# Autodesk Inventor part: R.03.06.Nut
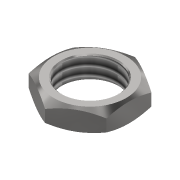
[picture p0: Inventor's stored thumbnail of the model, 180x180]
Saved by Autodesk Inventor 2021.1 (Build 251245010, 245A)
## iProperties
Created: 2021-02
Part Number: R.03.06.Nut
Material: Stainless Steel
Document SubType Name: Modeling
Designer: Михальчик
Density: 8 g/cm^3
Appearance: Semi-Polished
Author: Михальчик
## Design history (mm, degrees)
sketch "Sketch1"
  geometry: L1 (0, 0)-(0, 19.932); L2 (5, 0)-(8.5, 0); L3 (8.5, 0)-(8.5, 4); L4 (8.5, 4)-(5, 4); L5 (5, 4)-(5, 0); L6 (6.5, 4)-(8.5, 2.845); L7 (8.5, 1.155)-(6.5, 0)
  constraints: 14 end point, 5 point on line, 2 parallel, 1 equal length, 1 horizontal, 1 perpendicular, 1 vertical
  dimensions: "d0" = 10 diameter of L5 L1; "d1" = 17 diameter of L3 L1; "d2" = 4 distance of L2.end L3.end; "d3" = 150 deg angle of L4 L6; "d4" = 13 diameter of L6.start L1; "d5" = 30 deg angle of L2 L7
revolve "Revolution1" sketch "Sketch1" stored, may be unused: angle "d6" = 90 deg
thread "Thread1" dims "d7" = 4, "d8" = 0
chamfer "Chamfer1" distance "d9" = 0.2; stored, may be unused: second distance "d10" = 2, angle "d11" = 45 deg
sketch "Sketch2"
  geometry: L1 (0, 8.083)-(7, 4.041); L2 (7, 4.041)-(7, -4.041); L3 (7, -4.041)-(0, -8.083); L4 (0, -8.083)-(-7, -4.041); L5 (-7, -4.041)-(-7, 4.041); L6 (-7, 4.041)-(0, 8.083); C1 r 8.5 at (0, 0); 2 further points
  constraints: 12 end point, 1 centre point, 1 coincident, 13 other
  dimensions: "d12" = 14 distance between parallel lines of L2 L5
extrude "Extrusion1" cut sketch "Sketch2" distance "d13" = 10; taper "d14" = 0 deg
body "Solid1"
